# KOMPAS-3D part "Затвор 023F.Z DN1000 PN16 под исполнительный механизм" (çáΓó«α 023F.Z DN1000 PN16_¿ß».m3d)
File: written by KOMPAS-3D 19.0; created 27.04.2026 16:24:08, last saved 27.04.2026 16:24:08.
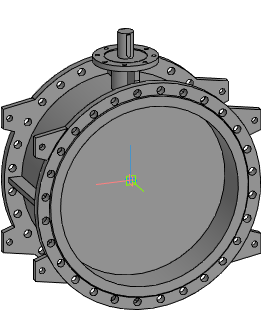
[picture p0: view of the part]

Document properties: Автор: Евгений; Полное имя файла: Z:\3.Личные\kachalov\3d для проектировщиков\1.7 Тип 023F.Z Затвор дисковый поворотный фланцевый с двумя эксцентриками\Затвор 023F.Z DN200-DN1600_исп\_stp_Затвор 023F.Z DN200-DN1600_исп\Затвор 023F.Z DN1000 PN16_исп.m3d

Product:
- Part/product: Затвор 023F.Z DN1000 PN16 под исполнительный механизм

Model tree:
1. Операция без истории:1  (labels: Затвор 023F.Z DN1000 PN16 под исполнительный механизм)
